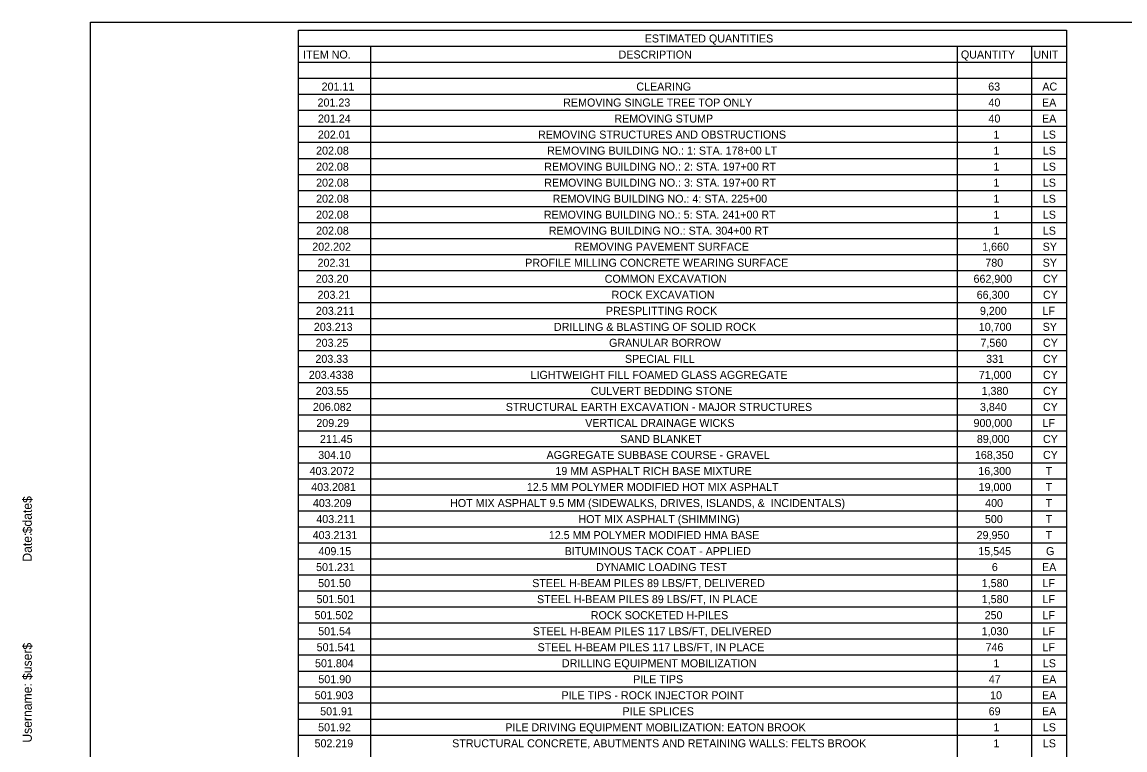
# Model space of a CAD drawing. Extents: x -18.7 to 5.6, y -2.7 to 4.
# Drawn here: x -9.864 to -8.508, y 3.09 to 3.985 of the extents above; entities that cross this region are included whole.
import ezdxf

# ---------------------------------------------------------------- set-up
doc = ezdxf.new("R2010")
doc.units = 0
doc.layers.add('ANNOTATION', color=7, linetype='Continuous')
doc.layers.add('BORDER', color=7, linetype='Continuous')

msp = doc.modelspace()

# ---------------------------------------------------------------- linework, layer by layer
at = {"layer": 'BORDER'}
for p, q in [((-9.524, 3.9551), (-8.5798, 3.9551)), ((-9.4355, 3.9551), (-9.4355, 2.2424)), ((-8.7141, 3.9551), (-8.7141, 2.2424)), ((-8.6227, 3.9551), (-8.6227, 2.2424)), ((-9.524, 3.9354), (-8.5798, 3.9354)), ((-9.524, 3.9157), (-8.5798, 3.9157)), ((-9.524, 3.896), (-8.5798, 3.896)), ((-9.524, 3.8764), (-8.5798, 3.8764)), ((-9.524, 3.8567), (-8.5798, 3.8567)), ((-9.524, 3.837), (-8.5798, 3.837)), ((-9.524, 3.8173), (-8.5798, 3.8173)), ((-9.524, 3.7976), (-8.5798, 3.7976)), ((-9.524, 3.7779), (-8.5798, 3.7779)), ((-9.524, 3.7582), (-8.5798, 3.7582)), ((-9.524, 3.7386), (-8.5798, 3.7386)), ((-9.524, 3.7189), (-8.5798, 3.7189)), ((-9.524, 3.6992), (-8.5798, 3.6992)), ((-9.524, 3.6795), (-8.5798, 3.6795)), ((-9.524, 3.6598), (-8.5798, 3.6598)), ((-9.524, 3.6401), (-8.5798, 3.6401)), ((-9.524, 3.6204), (-8.5798, 3.6204)), ((-9.524, 3.6008), (-8.5798, 3.6008)), ((-9.524, 3.5811), (-8.5798, 3.5811)), ((-9.524, 3.5614), (-8.5798, 3.5614)), ((-9.524, 3.5417), (-8.5798, 3.5417)), ((-9.524, 3.522), (-8.5798, 3.522)), ((-9.524, 3.5023), (-8.5798, 3.5023)), ((-9.524, 3.4826), (-8.5798, 3.4826)), ((-9.524, 3.463), (-8.5798, 3.463)), ((-9.524, 3.4433), (-8.5798, 3.4433)), ((-9.524, 3.4236), (-8.5798, 3.4236)), ((-9.524, 3.4039), (-8.5798, 3.4039)), ((-9.524, 3.3842), (-8.5798, 3.3842)), ((-9.524, 3.3645), (-8.5798, 3.3645)), ((-9.524, 3.3448), (-8.5798, 3.3448)), ((-9.524, 3.3251), (-8.5798, 3.3251)), ((-9.524, 3.3055), (-8.5798, 3.3055)), ((-9.524, 3.2858), (-8.5798, 3.2858)), ((-9.524, 3.2661), (-8.5798, 3.2661)), ((-9.524, 3.2464), (-8.5798, 3.2464)), ((-9.524, 3.2267), (-8.5798, 3.2267)), ((-9.524, 3.207), (-8.5798, 3.207)), ((-9.524, 3.1873), (-8.5798, 3.1873)), ((-9.524, 3.1677), (-8.5798, 3.1677)), ((-9.524, 3.148), (-8.5798, 3.148)), ((-9.524, 3.1283), (-8.5798, 3.1283)), ((-9.524, 3.1086), (-8.5798, 3.1086))]:
    msp.add_line(p, q, dxfattribs=at)
for points in [[(-9.7797, 3.9848), (-7.1131, 3.9848), (-7.1131, 2.2348), (-9.7797, 2.2348)], [(-9.524, 3.9748), (-8.5798, 3.9748), (-8.5798, 2.2424), (-9.524, 2.2424)]]:
    msp.add_lwpolyline(points, close=True, dxfattribs=at)

# ---------------------------------------------------------------- texts
at = {"layer": 'ANNOTATION'}
for s, height, p in [('201.11', 0.00984, (-9.4954, 3.9006)), ('CLEARING', 0.00984, (-9.1085, 3.9006)), ('63', 0.00984, (-8.6759, 3.9006)), ('AC', 0.00984, (-8.6094, 3.9006)), ('201.23', 0.00984, (-9.5004, 3.881)), ('REMOVING SINGLE TREE TOP ONLY', 0.009843, (-9.1984, 3.881)), ('40', 0.00984, (-8.6756, 3.881)), ('EA', 0.00984, (-8.6098, 3.881)), ('201.24', 0.00984, (-9.4999, 3.8613)), ('REMOVING STUMP', 0.009843, (-9.1355, 3.8613)), ('40', 0.00984, (-8.6756, 3.8613)), ('EA', 0.00984, (-8.6098, 3.8613)), ('202.01', 0.00984, (-9.5, 3.8416)), ('REMOVING STRUCTURES AND OBSTRUCTIONS', 0.009843, (-9.2294, 3.8416)), ('1', 0.00984, (-8.6695, 3.8416)), ('LS', 0.00984, (-8.6088, 3.8416)), ('202.08', 0.00984, (-9.5022, 3.8219)), ('REMOVING BUILDING NO.: 1: STA. 178+00 LT', 0.009843, (-9.2181, 3.8219)), ('1', 0.00984, (-8.6695, 3.8219)), ('LS', 0.00984, (-8.6088, 3.8219)), ('202.08', 0.00984, (-9.5022, 3.8022)), ('REMOVING BUILDING NO.: 2: STA. 197+00 RT', 0.009843, (-9.2217, 3.8022)), ('1', 0.00984, (-8.6695, 3.8022)), ('LS', 0.00984, (-8.6088, 3.8022)), ('202.08', 0.00984, (-9.5022, 3.7825)), ('REMOVING BUILDING NO.: 3: STA. 197+00 RT', 0.009843, (-9.2217, 3.7825)), ('1', 0.00984, (-8.6695, 3.7825)), ('LS', 0.00984, (-8.6088, 3.7825)), ('202.08', 0.00984, (-9.5022, 3.7628)), ('REMOVING BUILDING NO.: 4: STA. 225+00', 0.009843, (-9.2114, 3.7628)), ('1', 0.00984, (-8.6695, 3.7628)), ('LS', 0.00984, (-8.6088, 3.7628)), ('202.08', 0.00984, (-9.5022, 3.7432)), ('REMOVING BUILDING NO.: 5: STA. 241+00 RT', 0.009843, (-9.2222, 3.7432)), ('1', 0.00984, (-8.6695, 3.7432)), ('LS', 0.00984, (-8.6088, 3.7432)), ('202.08', 0.00984, (-9.5022, 3.7235)), ('REMOVING BUILDING NO.: STA. 304+00 RT', 0.009843, (-9.2161, 3.7235)), ('1', 0.00984, (-8.6695, 3.7235)), ('LS', 0.00984, (-8.6088, 3.7235)), ('202.202', 0.00984, (-9.5069, 3.7038)), ('REMOVING PAVEMENT SURFACE', 0.009843, (-9.1844, 3.7038)), ('1,660', 0.00984, (-8.6834, 3.7038)), ('SY', 0.00984, (-8.609, 3.7038)), ('202.31', 0.00984, (-9.5004, 3.6841)), ('PROFILE MILLING CONCRETE WEARING SURFACE', 0.009843, (-9.2451, 3.6841)), ('780', 0.00984, (-8.6795, 3.6841)), ('SY', 0.00984, (-8.609, 3.6841)), ('203.20', 0.00984, (-9.5026, 3.6644)), ('COMMON EXCAVATION', 0.009843, (-9.1474, 3.6644)), ('662,900', 0.00984, (-8.694, 3.6644)), ('CY', 0.00984, (-8.6086, 3.6644)), ('203.21', 0.00984, (-9.5004, 3.6447)), ('ROCK EXCAVATION', 0.009843, (-9.1389, 3.6447)), ('66,300', 0.00984, (-8.6901, 3.6447)), ('CY', 0.00984, (-8.6086, 3.6447)), ('203.211', 0.00984, (-9.5024, 3.625)), ('PRESPLITTING ROCK', 0.009843, (-9.1459, 3.625)), ('9,200', 0.00984, (-8.6861, 3.625)), ('LF', 0.00984, (-8.6092, 3.625)), ('203.213', 0.00984, (-9.5049, 3.6053)), ('DRILLING & BLASTING OF SOLID ROCK       ', 0.009843, (-9.2098, 3.6053)), ('10,700', 0.00984, (-8.6875, 3.6053)), ('SY', 0.00984, (-8.609, 3.6053)), ('203.25', 0.00984, (-9.5027, 3.5857)), ('GRANULAR BORROW', 0.009843, (-9.1421, 3.5857)), ('7,560', 0.00984, (-8.6855, 3.5857)), ('CY', 0.00984, (-8.6086, 3.5857)), ('203.33', 0.00984, (-9.503, 3.566)), ('SPECIAL FILL', 0.009843, (-9.1225, 3.566)), ('331', 0.00984, (-8.6785, 3.566)), ('CY', 0.00984, (-8.6086, 3.566)), ('203.4338', 0.00984, (-9.5111, 3.5463)), ('LIGHTWEIGHT FILL FOAMED GLASS AGGREGATE', 0.009843, (-9.2385, 3.5463)), ('71,000', 0.00984, (-8.6875, 3.5463)), ('CY', 0.00984, (-8.6086, 3.5463)), ('203.55', 0.00984, (-9.5026, 3.5266)), ('CULVERT BEDDING STONE', 0.009843, (-9.1645, 3.5266)), ('1,380', 0.00984, (-8.6841, 3.5266)), ('CY', 0.00984, (-8.6086, 3.5266)), ('206.082', 0.00984, (-9.5061, 3.5069)), ('STRUCTURAL EARTH EXCAVATION - MAJOR STRUCTURES', 0.009843, (-9.269, 3.5069)), ('3,840', 0.00984, (-8.6861, 3.5069)), ('CY', 0.00984, (-8.6086, 3.5069)), ('209.29', 0.00984, (-9.5019, 3.4872)), ('VERTICAL DRAINAGE WICKS', 0.009843, (-9.1714, 3.4872)), ('900,000', 0.00984, (-8.694, 3.4872)), ('LF', 0.00984, (-8.6092, 3.4872)), ('211.45', 0.00984, (-9.4975, 3.4675)), ('SAND BLANKET', 0.009843, (-9.1284, 3.4675)), ('89,000', 0.00984, (-8.6899, 3.4675)), ('CY', 0.00984, (-8.6086, 3.4675)), ('304.10', 0.00984, (-9.4996, 3.4479)), ('AGGREGATE SUBBASE COURSE - GRAVEL', 0.009843, (-9.2189, 3.4479)), ('168,350', 0.00984, (-8.6923, 3.4479)), ('CY', 0.00984, (-8.6086, 3.4479)), ('403.2072', 0.00984, (-9.5102, 3.4282)), ('19 MM ASPHALT RICH BASE MIXTURE', 0.009843, (-9.208, 3.4282)), ('16,300', 0.00984, (-8.6881, 3.4282)), ('T', 0.00984, (-8.6053, 3.4282)), ('403.2081', 0.00984, (-9.5082, 3.4085)), ('12.5 MM POLYMER MODIFIED HOT MIX ASPHALT', 0.009843, (-9.2431, 3.4085)), ('19,000', 0.00984, (-8.6877, 3.4085)), ('T', 0.00984, (-8.6053, 3.4085)), ('403.209', 0.00984, (-9.5061, 3.3888)), ('HOT MIX ASPHALT 9.5 MM (SIDEWALKS, DRIVES, ISLANDS, &  INCIDENTALS)', 0.009843, (-9.3375, 3.3888)), ('400', 0.00984, (-8.6797, 3.3888)), ('T', 0.00984, (-8.6053, 3.3888)), ('403.211', 0.00984, (-9.5019, 3.3691)), ('HOT MIX ASPHALT (SHIMMING)', 0.009843, (-9.1797, 3.3691)), ('500', 0.00984, (-8.68, 3.3691)), ('T', 0.00984, (-8.6053, 3.3691)), ('403.2131', 0.00984, (-9.5064, 3.3494)), ('12.5 MM POLYMER MODIFIED HMA BASE', 0.009843, (-9.2161, 3.3494)), ('29,950', 0.00984, (-8.6902, 3.3494)), ('T', 0.00984, (-8.6053, 3.3494)), ('409.15', 0.00984, (-9.4992, 3.3297)), ('BITUMINOUS TACK COAT - APPLIED', 0.009843, (-9.1966, 3.3297)), ('15,545', 0.00984, (-8.6881, 3.3297)), ('G', 0.00984, (-8.6049, 3.3297)), ('501.231', 0.00984, (-9.5022, 3.3101)), ('DYNAMIC LOADING TEST', 0.009843, (-9.158, 3.3101)), ('6', 0.00984, (-8.6715, 3.3101)), ('EA', 0.00984, (-8.6098, 3.3101)), ('501.50', 0.00984, (-9.4997, 3.2904)), ('STEEL H-BEAM PILES 89 LBS/FT, DELIVERED', 0.009843, (-9.2365, 3.2904)), ('1,580', 0.00984, (-8.6839, 3.2904)), ('LF', 0.00984, (-8.6092, 3.2904)), ('501.501', 0.00984, (-9.5017, 3.2707)), ('STEEL H-BEAM PILES 89 LBS/FT, IN PLACE', 0.009843, (-9.2306, 3.2707)), ('1,580', 0.00984, (-8.6839, 3.2707)), ('LF', 0.00984, (-8.6092, 3.2707)), ('501.502', 0.00984, (-9.5041, 3.251)), ('ROCK SOCKETED H-PILES', 0.009843, (-9.1645, 3.251)), ('250', 0.00984, (-8.6803, 3.251)), ('LF', 0.00984, (-8.6092, 3.251)), ('501.54', 0.00984, (-9.4996, 3.2313)), ('STEEL H-BEAM PILES 117 LBS/FT, DELIVERED', 0.009843, (-9.2358, 3.2313)), ('1,030', 0.00984, (-8.6841, 3.2313)), ('LF', 0.00984, (-8.6092, 3.2313)), ('501.541', 0.00984, (-9.5015, 3.2116)), ('STEEL H-BEAM PILES 117 LBS/FT, IN PLACE', 0.009843, (-9.2299, 3.2116)), ('746', 0.00984, (-8.6792, 3.2116)), ('LF', 0.00984, (-8.6092, 3.2116)), ('501.804', 0.00984, (-9.5035, 3.1919)), ('DRILLING EQUIPMENT MOBILIZATION', 0.009843, (-9.2, 3.1919)), ('1', 0.00984, (-8.6695, 3.1919)), ('LS', 0.00984, (-8.6088, 3.1919)), ('501.90', 0.00984, (-9.4994, 3.1723)), ('PILE TIPS', 0.00984, (-9.1124, 3.1723)), ('47', 0.00984, (-8.6752, 3.1723)), ('EA', 0.00984, (-8.6098, 3.1723)), ('501.903', 0.00984, (-9.5039, 3.1526)), ('PILE TIPS - ROCK INJECTOR POINT', 0.009843, (-9.2006, 3.1526)), ('10', 0.00984, (-8.6736, 3.1526)), ('EA', 0.00984, (-8.6098, 3.1526)), ('501.91', 0.00984, (-9.4972, 3.1329)), ('PILE SPLICES', 0.009843, (-9.1255, 3.1329)), ('69', 0.00984, (-8.6754, 3.1329)), ('EA', 0.00984, (-8.6098, 3.1329)), ('501.92', 0.00984, (-9.4997, 3.1132)), ('PILE DRIVING EQUIPMENT MOBILIZATION: EATON BROOK', 0.009843, (-9.2696, 3.1132)), ('1', 0.00984, (-8.6695, 3.1132)), ('LS', 0.00984, (-8.6088, 3.1132)), ('502.219', 0.00984, (-9.5041, 3.0935)), ('STRUCTURAL CONCRETE, ABUTMENTS AND RETAINING WALLS: FELTS BROOK', 0.009843, (-9.3349, 3.0935)), ('1', 0.00984, (-8.6695, 3.0935)), ('LS', 0.00984, (-8.6088, 3.0935))]:
    msp.add_text(s, height=height, dxfattribs=at).set_placement(p)
at = {"layer": 'BORDER'}
for s, height, p in [('ESTIMATED QUANTITIES', 0.009843, (-9.0982, 3.9597)), ('ITEM NO.', 0.00984, (-9.5181, 3.94)), ('DESCRIPTION', 0.009843, (-9.1303, 3.94)), ('QUANTITY', 0.00984, (-8.7095, 3.94)), ('UNIT', 0.00984, (-8.6204, 3.94))]:
    msp.add_text(s, height=height, dxfattribs=at).set_placement(p)
for s, p in [('$date$', (-9.8517, 3.3565)), ('Date:', (-9.8517, 3.3217)), ('$user$', (-9.8517, 3.1763)), ('Username:', (-9.8517, 3.0993))]:
    msp.add_text(s, height=0.01116, rotation=90, dxfattribs=at).set_placement(p)

doc.saveas('drawing.dxf')
